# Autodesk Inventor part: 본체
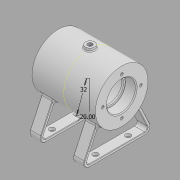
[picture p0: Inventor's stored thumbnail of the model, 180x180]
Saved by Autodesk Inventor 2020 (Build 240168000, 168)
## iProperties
Created: 2021-12
Part Number: 본체
Material: 일반
Document SubType Name: Modeling
Designer: MIRAE
Density: 1 g/cm^3
Appearance: 기본값
Mass: 114.909 g
Surface Area: 354.98 cm^2
Volume: 114.909 cm^3
Author: MIRAE
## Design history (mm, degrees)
sketch "스케치1"
  geometry: L1 (0, 0)-(70, 0); L2 (70, 0)-(70, 29); L3 (70, 29)-(0, 29); L4 (0, 29)-(0, 0); L5 (0, 16)-(12, 16); L6 (12, 16)-(12, 14); L7 (12, 14)-(14, 14); L8 (14, 14)-(14, 21); L9 (14, 21)-(56, 21); L10 (56, 21)-(56, 14); L11 (56, 14)-(58, 14); L12 (58, 14)-(58, 16); L13 (58, 16)-(70, 16)
  constraints: 26 end point, 7 perpendicular, 5 point on line, 3 horizontal, 2 parallel
  dimensions: "d0" = 58 diameter of L3 L1; "d1" = 70 distance of L2.end L3.end; "d5" = 32 diameter of L13 L1; "d6" = 28 diameter of L11 L1; "d7" = 42 diameter of L9 L1; "d8" = 12 distance of L12.end L13.end; "d9" = 42 distance of L8.end L9.end; "d10" = 2 distance of L10.end L11.end; "d11" = 2 distance of L6.end L7.end
revolve "회전1" sketch "스케치1" stored, may be unused: angle "d12" = 90 deg
node "작업 평면1"
sketch "스케치2"
  geometry: L1 (0, -55)-(40, -55); L2 (40, -55)-(22.743, -17.993); L3 (0, -52)-(35.291, -52); L4 (35.291, -52)-(20.574, -20.438); L5 (0, -29)-(0, -62.069); L6 (-40, -55)-(-22.743, -17.993); L7 (-35.291, -52)-(-20.574, -20.438); L8 (0, -52)-(-35.291, -52); L9 (0, -55)-(-40, -55); C1 r 16 at (0, 0) reference; A1 r 29 centre (0, 0) between (-22.743, -17.993) and (22.743, -17.993) reference; A2 r 29 centre (0, 0) between (-22.743, -17.993) and (22.743, -17.993); A3 r 29 centre (0, 0) between (-22.743, -17.993) and (22.743, -17.993); 9 further points
  constraints: 18 end point, 9 point on circle, 9 point on line, 4 symmetric about line, 2 centre point, 2 concentric, 2 horizontal, 2 horizontal alignment, 1 parallel, 1 vertical
  dimensions: "d14" = 3 distance between parallel lines of L4 L2; "d15" = 3 distance between parallel lines of L1 L3; "d17" = 65 deg angle of L1 L2; "d19" = 55 distance from line of L1 point (0, 0); "d85" = 80 distance of point (40, -55) L6.start
extrude "돌출1" join sketch "스케치2" distance "d22" = 12; taper "d23" = 0 deg
node "작업 평면2"
sketch "스케치3" dims "d30" = 42
  geometry: 3 further points
  constraints: 2 vertical alignment, 1 coincident, 2 other
hole "구멍1" sketch "스케치3" at (0, 21) diameter "d31" = 3.242; stored, may be unused: countersink angle "d35" = 90 deg, drill point angle "d37" = 118 deg; dims "d32" = 8, "d33" = 4, "d34" = 2, "d36" = 10
sketch "스케치4"
  geometry: L1 (0, 0)-(0, 31.346); L2 (0, 0)-(10.945, -30.07); C1 r 29 at (0, 0) reference; C2 r 21 at (0, 0) reference; 1 further point
  constraints: 4 end point, 1 vertical
  dimensions: "d41" = 20 deg angle of L2 L1; "d42" = 32 distance of L1.start L2.end
  node "절단 모서리 투영2"
node "작업 평면4"
sketch "스케치5"
  geometry: C1 r 6 at (0, 0); 4 further points
  constraints: 1 centre point, 1 coincident
  dimensions: "d43" = 12 diameter of C1
extrude "돌출2" join sketch "스케치5" stored distance "d44" = 12; taper "d45" = 0 deg
sketch "스케치6"
  geometry: C1 r 6 at (0, 0) reference; 2 further points
  constraints: 1 coincident
hole "구멍2" sketch "스케치6" at (0, 0) diameter "d46" = 5.1881; stored, may be unused: countersink angle "d50" = 90 deg, drill point angle "d52" = 0 deg; dims "d47" = 12, "d48" = 4, "d49" = 2, "d51" = 16
node "작업 평면5"
sketch "스케치7"
  geometry: C1 r 5 at (-35, 0); 2 further points
  constraints: 1 centre point, 1 coincident
  dimensions: "d54" = 10 diameter of C1
extrude "돌출3" join sketch "스케치7" stored distance "d55" = 12; taper "d56" = 0 deg
sketch "스케치8"
  geometry: C1 r 5 at (0, 0) reference; 2 further points
  constraints: 1 coincident
hole "구멍3" sketch "스케치8" at (0, 0) diameter "d57" = 5.1881; stored, may be unused: countersink angle "d61" = 90 deg, drill point angle "d63" = 118 deg; dims "d58" = 6, "d59" = 4, "d60" = 2, "d62" = 8
sketch "스케치9"
  geometry: C1 r 5 at (0, 0) reference; 2 further points
  constraints: 1 coincident
hole "구멍4" sketch "스케치9" at (0, 0) diameter "d64" = 3; stored, may be unused: countersink angle "d68" = 90 deg, drill point angle "d70" = 118 deg; dims "d65" = 6, "d66" = 4, "d67" = 2, "d69" = 8
fillet "모깎기1" dims "d71" = 3
fillet "모깎기2" dims "d72" = 0.3
chamfer "모따기1" distance "d73" = 1; stored, may be unused: second distance "d74" = 2, angle "d75" = 45 deg
fillet "모깎기3" dims "d84" = 1
fillet "모깎기4" dims "d86" = 6
fillet "모깎기5" dims "d87" = 3
sketch "스케치11"
  geometry: L1 (60, -5.196)-(48, -5.196) reference; L2 (48, -5.196)-(48, 0) reference; L3 (48, 0)-(60, 0) reference; L4 (60, 61.164)-(60, 0) reference; L5 (48, 61.164)-(60, 61.164) reference; L6 (48, 61.164)-(48, 66.36) reference; L7 (48, 66.36)-(60, 66.36) reference; L8 (60, 66.36)-(60, 61.164) reference; L9 (60, 0)-(60, -5.196) reference; L10 (48, 0)-(48, 61.164) reference; L11 (12, -5.196)-(0, -5.196) reference; L12 (0, -5.196)-(0, 0) reference; L13 (12, 0)-(0, 0) reference; L14 (12, 61.164)-(12, 0) reference; L15 (12, 61.164)-(0, 61.164) reference; L16 (0, 61.164)-(0, 66.36) reference; L17 (0, 66.36)-(12, 66.36) reference; L18 (12, 66.36)-(12, 61.164) reference; L19 (12, 0)-(12, -5.196) reference; L20 (0, 0)-(0, 61.164) reference; L21 (60, 30.582)-(20.011, 30.582); 6 further points
  constraints: 2 end point, 2 midpoint, 2 vertical alignment, 1 horizontal, 1 horizontal alignment, 1 symmetric about line
  dimensions: "d96" = 48 distance of point (6, 12.582) point (54, 12.582); "d97" = 36 distance of point (6, 48.582) point (6, 12.582); "d98" = 48 distance of point (6, 48.582) point (54, 48.582)
hole "구멍7" sketch "스케치11" at (6, 48.582), (6, 12.582), (54, 48.582), (54, 12.582) diameter "d99" = 6; stored, may be unused: countersink angle "d103" = 90 deg, drill point angle "d105" = 118 deg; dims "d100" = 6, "d101" = 4, "d102" = 2, "d104" = 8
fillet "모깎기6" dims "d106" = 0.5
fillet "모깎기7" dims "d107" = 3
fillet "모깎기8" dims "d108" = 1
node "작업 평면6"
sketch "스케치12"
  geometry: L1 (-20.739, 3.002)-(20.739, 3.002); L2 (20.739, 3.002)-(20.739, -3.002); L3 (20.739, -3.002)-(-20.739, -3.002); L4 (-20.739, -3.002)-(-20.739, 3.002); L5 (-20.739, 3.002)-(20.739, -3.002); L6 (-35, 29)-(-35, -29) reference; 2 further points
  constraints: 2 end point, 1 midpoint, 2 other
  dimensions: "d109" = 35 distance from line of point (0, 0) L6; "d110" = 29 vertical distance of L6.start point (0, 0)
feature "엠보싱1" sketch "스케치12" dims "d0" = 58, "d1" = 70, "d5" = 32, "d6" = 28, "d7" = 42, "d8" = 12, "d9" = 42, "d10" = 2, "d11" = 2, "d14" = 3, "d15" = 3, "d17" = 65 deg, "d19" = 55, "d85" = 80, "d111" = 0.5, "d112" = 0
node "솔리드1"
mirror "미러1"
pattern_circular "원형 패턴1" dims angle "d39" = 360 deg
mirror "미러2"
node "작업 평면3"
node "절단 모서리 투영1"
node "절단 모서리 투영4"
feature "A9D066F2-1C7D-4E18-AEED-F7BC21143FA4" dims "d99" = 6, "d100" = 6, "d101" = 4, "d102" = 2, "d103" = 90 deg, "d104" = 8, "d105" = 118 deg
other parameters: "d13" = -5, "d53" = 32
